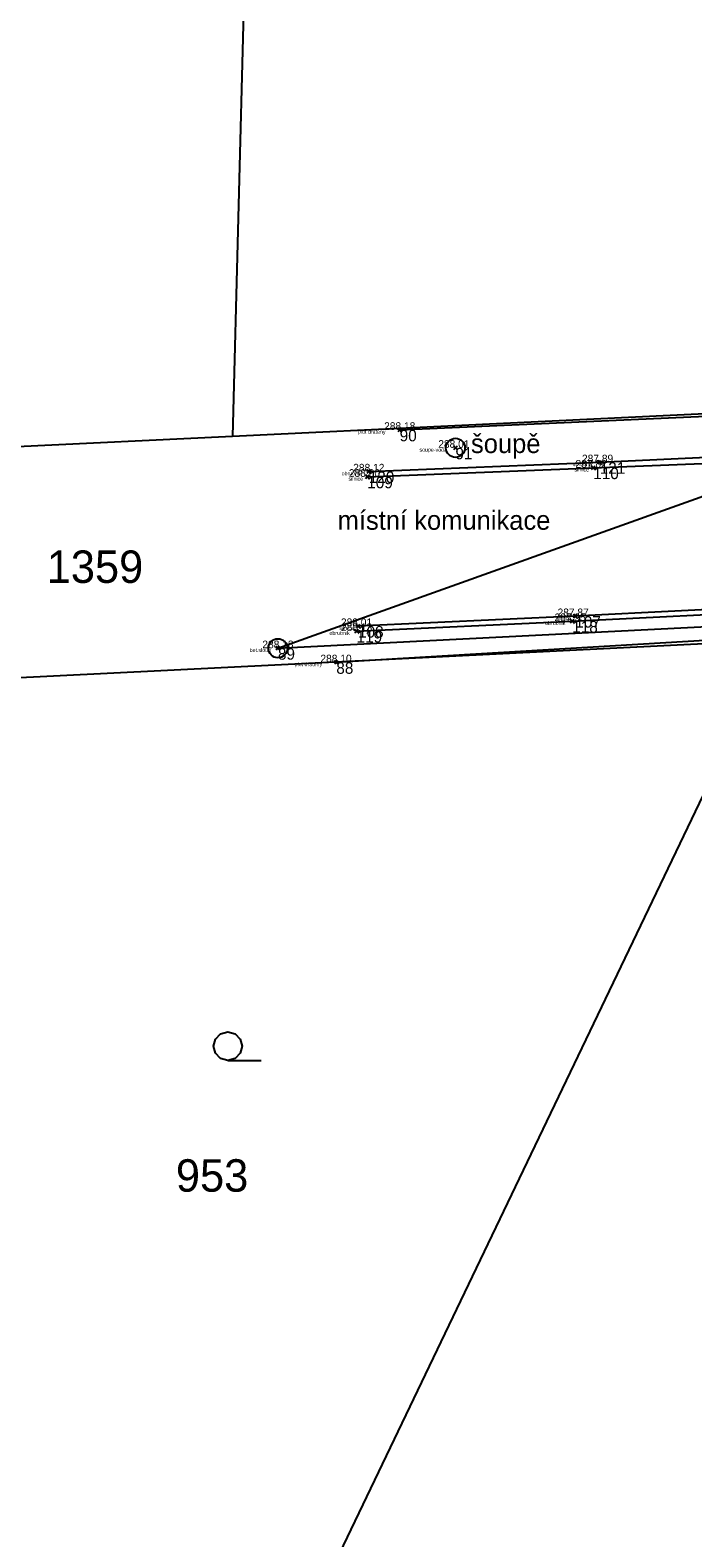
# Model space of a CAD drawing. Extents: x -456675 to -456278, y -1112395 to -1112217.
# Drawn here: x -456598.34 to -456580.98, y -1112328.73 to -1112289.23 of the extents above; entities that cross this region are included whole.
import ezdxf

# ---------------------------------------------------------------- set-up
doc = ezdxf.new("R2010")
doc.units = 0
for name, color, linetype in [('Cislo_bodu', 7, 'Continuous'), ('g_CETIN', 7, 'Continuous'), ('g_elektrina', 7, 'Continuous'), ('g_komunikace', 7, 'Continuous'), ('g_obrubnik', 7, 'Continuous'), ('g_ploty', 7, 'Continuous'), ('g_voda', 7, 'Continuous'), ('Katastralni_mapa', 7, 'Continuous'), ('Kod_bodu', 7, 'Continuous'), ('Vyska_bodu', 7, 'Continuous'), ('Znacka_bodu', 7, 'Continuous')]:
    doc.layers.add(name, color=color, linetype=linetype)

msp = doc.modelspace()

# ---------------------------------------------------------------- linework, layer by layer
at = {"layer": 'g_CETIN'}
msp.add_line((-456591.85, -1112305.42), (-456577.53, -1112300.29), dxfattribs=at)
at = {"layer": 'g_elektrina'}
msp.add_line((-456591.85, -1112305.42), (-456562.97, -1112303.96), dxfattribs=at)
msp.add_circle((-456591.85, -1112305.42), 0.25, dxfattribs=at)
at = {"layer": 'g_komunikace'}
msp.add_lwpolyline([(-456589.51, -1112300.93), (-456583.59, -1112300.69), (-456578.53, -1112300.49), (-456578.5, -1112302.33), (-456578.75, -1112302.36), (-456578.68, -1112303.1), (-456578.57, -1112303.16), (-456578.49, -1112304.3), (-456584.06, -1112304.58), (-456589.75, -1112304.84)], dxfattribs=at)
at = {"layer": 'g_obrubnik'}
for points in [[(-456589.47, -1112300.79), (-456583.42, -1112300.55), (-456578.38, -1112300.31), (-456578.38, -1112302.27)], [(-456589.79, -1112304.97), (-456584.14, -1112304.71), (-456578.49, -1112304.43)]]:
    msp.add_lwpolyline(points, dxfattribs=at)
at = {"layer": 'g_ploty'}
for points in [[(-456588.66, -1112299.7), (-456577.12, -1112299.18), (-456570.18, -1112298.84), (-456563.86, -1112298.52), (-456563.69, -1112291.41), (-456563.68, -1112287.66)], [(-456564.24, -1112317.5), (-456564.14, -1112310.05), (-456564.09, -1112304.42), (-456570.24, -1112304.71), (-456578.76, -1112305.1), (-456590.32, -1112305.79)]]:
    msp.add_lwpolyline(points, dxfattribs=at)
at = {"layer": 'g_voda'}
msp.add_circle((-456587.2, -1112300.17), 0.25, dxfattribs=at)
at = {"layer": 'Katastralni_mapa'}
for points in [[(-456592.74, -1112288.41), (-456593.04, -1112299.87)], [(-456563.92, -1112298.48), (-456593.04, -1112299.87)], [(-456593.04, -1112299.87), (-456598.86, -1112300.15)], [(-456600.55, -1112306.28), (-456578.75, -1112305.2)], [(-456590.54, -1112329.78), (-456578.75, -1112305.2)], [(-456593.16, -1112316.22), (-456593.35, -1112316.17), (-456593.485, -1112316.03), (-456593.535, -1112315.845), (-456593.485, -1112315.66), (-456593.35, -1112315.52), (-456593.16, -1112315.47), (-456592.97, -1112315.52), (-456592.835, -1112315.66), (-456592.785, -1112315.845), (-456592.835, -1112316.03), (-456592.97, -1112316.17), (-456593.16, -1112316.22), (-456592.285, -1112316.22)]]:
    msp.add_lwpolyline(points, dxfattribs=at)
at = {"layer": 'Znacka_bodu'}
for p, q in [((-456588.66, -1112299.7), (-456588.71, -1112299.65)), ((-456588.66, -1112299.7), (-456588.71, -1112299.75)), ((-456588.66, -1112299.7), (-456588.61, -1112299.65)), ((-456588.66, -1112299.7), (-456588.61, -1112299.75)), ((-456587.2, -1112300.17), (-456587.25, -1112300.12)), ((-456587.2, -1112300.17), (-456587.15, -1112300.12)), ((-456587.2, -1112300.17), (-456587.25, -1112300.22)), ((-456587.2, -1112300.17), (-456587.15, -1112300.22)), ((-456583.42, -1112300.55), (-456583.47, -1112300.5)), ((-456583.42, -1112300.55), (-456583.47, -1112300.6)), ((-456583.42, -1112300.55), (-456583.37, -1112300.5)), ((-456583.42, -1112300.55), (-456583.37, -1112300.6)), ((-456589.51, -1112300.93), (-456589.56, -1112300.88)), ((-456589.51, -1112300.93), (-456589.56, -1112300.98)), ((-456589.47, -1112300.79), (-456589.52, -1112300.74)), ((-456589.47, -1112300.79), (-456589.52, -1112300.84)), ((-456589.51, -1112300.93), (-456589.46, -1112300.88)), ((-456589.51, -1112300.93), (-456589.46, -1112300.98)), ((-456589.47, -1112300.79), (-456589.42, -1112300.74)), ((-456589.47, -1112300.79), (-456589.42, -1112300.84)), ((-456583.59, -1112300.69), (-456583.64, -1112300.64)), ((-456583.59, -1112300.69), (-456583.64, -1112300.74)), ((-456583.59, -1112300.69), (-456583.54, -1112300.64)), ((-456583.59, -1112300.69), (-456583.54, -1112300.74)), ((-456589.75, -1112304.84), (-456589.8, -1112304.79)), ((-456589.75, -1112304.84), (-456589.8, -1112304.89)), ((-456589.75, -1112304.84), (-456589.7, -1112304.79)), ((-456589.75, -1112304.84), (-456589.7, -1112304.89)), ((-456584.14, -1112304.71), (-456584.19, -1112304.66)), ((-456584.14, -1112304.71), (-456584.19, -1112304.76)), ((-456584.14, -1112304.71), (-456584.09, -1112304.66)), ((-456584.14, -1112304.71), (-456584.09, -1112304.76)), ((-456584.06, -1112304.58), (-456584.11, -1112304.53)), ((-456584.06, -1112304.58), (-456584.11, -1112304.63)), ((-456584.06, -1112304.58), (-456584.01, -1112304.53)), ((-456584.06, -1112304.58), (-456584.01, -1112304.63)), ((-456589.79, -1112304.97), (-456589.84, -1112304.92)), ((-456589.79, -1112304.97), (-456589.84, -1112305.02)), ((-456589.79, -1112304.97), (-456589.74, -1112304.92)), ((-456589.79, -1112304.97), (-456589.74, -1112305.02)), ((-456591.85, -1112305.42), (-456591.9, -1112305.37)), ((-456591.85, -1112305.42), (-456591.9, -1112305.47)), ((-456591.85, -1112305.42), (-456591.8, -1112305.37)), ((-456591.85, -1112305.42), (-456591.8, -1112305.47)), ((-456590.32, -1112305.79), (-456590.37, -1112305.74)), ((-456590.32, -1112305.79), (-456590.37, -1112305.84)), ((-456590.32, -1112305.79), (-456590.27, -1112305.74)), ((-456590.32, -1112305.79), (-456590.27, -1112305.84))]:
    msp.add_line(p, q, dxfattribs=at)

# ---------------------------------------------------------------- texts
at = {"layer": 'Cislo_bodu'}
for s, p in [('90', (-456588.66, -1112300)), ('91', (-456587.2, -1112300.47)), ('121', (-456583.42, -1112300.85)), ('109', (-456589.51, -1112301.23)), ('120', (-456589.47, -1112301.09)), ('110', (-456583.59, -1112300.99)), ('108', (-456589.75, -1112305.14)), ('118', (-456584.14, -1112305.01)), ('107', (-456584.06, -1112304.88)), ('119', (-456589.79, -1112305.27)), ('89', (-456591.85, -1112305.72)), ('88', (-456590.32, -1112306.09))]:
    msp.add_text(s, height=0.3, dxfattribs=at).set_placement(p)
at = {"layer": 'g_komunikace'}
msp.add_text('místní komunikace', height=0.5, dxfattribs=at).set_placement((-456590.286, -1112302.316))
at = {"layer": 'g_voda'}
msp.add_text('šoupě', height=0.5, dxfattribs=at).set_placement((-456586.793, -1112300.307))
at = {"layer": 'Katastralni_mapa'}
for s, p in [('1359', (-456597.907, -1112303.709)), ('953', (-456594.523, -1112319.657))]:
    msp.add_text(s, height=0.85, dxfattribs=at).set_placement(p)
at = {"layer": 'Kod_bodu'}
for s, p in [('plot drateny', (-456589.753, -1112299.8)), ('soupe-voda', (-456588.142, -1112300.27)), ('obrubnik', (-456584.13, -1112300.65)), ('obrubnik', (-456590.18, -1112300.89)), ('silnice', (-456590.001, -1112301.03)), ('silnice', (-456584.081, -1112300.79)), ('silnice', (-456590.241, -1112304.94)), ('obrubnik', (-456584.85, -1112304.81)), ('silnice', (-456584.551, -1112304.68)), ('obrubnik', (-456590.5, -1112305.07)), ('bet.sloup', (-456592.59, -1112305.52)), ('plot drateny', (-456591.413, -1112305.89))]:
    msp.add_text(s, height=0.1, dxfattribs=at).set_placement(p)
at = {"layer": 'Vyska_bodu'}
for s, p in [('288.18', (-456589.068, -1112299.7)), ('288.01', (-456587.65, -1112300.17)), ('287.82', (-456584.055, -1112300.69)), ('287.89', (-456583.885, -1112300.55)), ('288.00', (-456589.992, -1112300.93)), ('288.12', (-456589.878, -1112300.79)), ('287.95', (-456584.605, -1112304.71)), ('287.87', (-456584.525, -1112304.58)), ('288.01', (-456590.2, -1112304.84)), ('288.13', (-456590.198, -1112304.97)), ('288.18', (-456592.258, -1112305.42)), ('288.10', (-456590.737, -1112305.79))]:
    msp.add_text(s, height=0.2, dxfattribs=at).set_placement(p)

doc.saveas('drawing.dxf')
